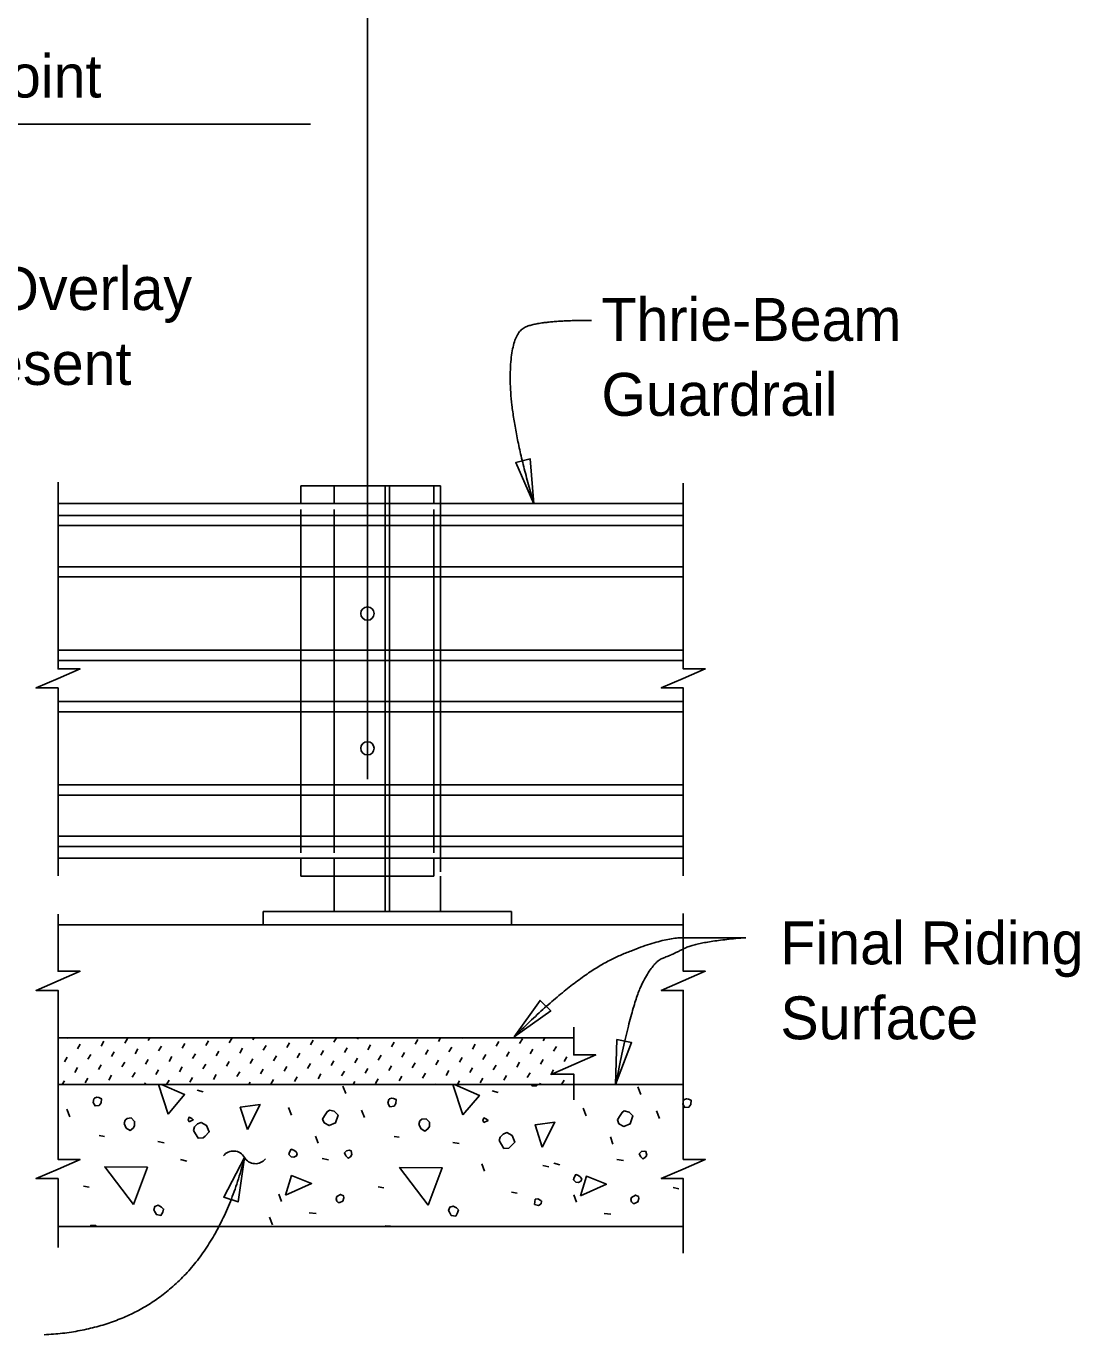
# Model space of a CAD drawing. Extents: x 21629.5 to 21698.8, y 56199.1 to 56237.6.
# Drawn here: x 21645.71 to 21650.66, y 56213.58 to 56219.73 of the extents above; entities that cross this region are included whole.
import ezdxf

# ---------------------------------------------------------------- set-up
doc = ezdxf.new("R2010")
doc.units = 0
for name, color, linetype in [('Dimension', 7, 'Continuous'), ('ExistSuperStruct', 7, 'Continuous'), ('Miscellaneous', 7, 'Continuous'), ('SteelMisc', 7, 'Continuous'), ('SteelMisc_h', 7, 'Continuous'), ('TextStructures', 7, 'Continuous')]:
    doc.layers.add(name, color=color, linetype=linetype)

msp = doc.modelspace()

# ---------------------------------------------------------------- linework, layer by layer
at = {"layer": 'Dimension'}
for p, q in [((21647.316, 56216.1894), (21647.316, 56231.405)), ((21647.048, 56219.267), (21641.4764, 56219.267))]:
    msp.add_line(p, q, dxfattribs=at)
for points in [[(21648.0978, 56217.4829), (21648.0807, 56217.6934), (21648.0123, 56217.676)], [(21648.0044, 56214.9776), (21648.1766, 56215.0999), (21648.1267, 56215.1498)], [(21648.4818, 56214.754), (21648.5565, 56214.9516), (21648.4873, 56214.9652)], [(21646.739, 56214.4119), (21646.7086, 56214.2029), (21646.6414, 56214.2246)]]:
    msp.add_lwpolyline(points, close=True, dxfattribs=at)
for points in [[(21645.8635, 56215.734), (21645.8635, 56216.6173), (21645.7601, 56216.6173), (21645.8635, 56216.6623), (21645.9668, 56216.7073), (21645.8635, 56216.7073), (21645.8635, 56217.5837)], [(21648.799, 56215.734), (21648.799, 56216.6173), (21648.6957, 56216.6173), (21648.799, 56216.6623), (21648.9023, 56216.7073), (21648.799, 56216.7073), (21648.799, 56217.5802)], [(21645.8635, 56214.7266), (21645.8635, 56215.1966), (21645.7601, 56215.1966), (21645.8635, 56215.2416), (21645.9668, 56215.2866), (21645.8635, 56215.2866), (21645.8635, 56215.5547)], [(21648.799, 56214.7266), (21648.799, 56215.1966), (21648.6957, 56215.1966), (21648.799, 56215.2416), (21648.9023, 56215.2866), (21648.799, 56215.2866), (21648.799, 56215.5576)], [(21648.2848, 56214.6826), (21648.2848, 56214.8035), (21648.1815, 56214.8035), (21648.2848, 56214.8485), (21648.3882, 56214.8935), (21648.2848, 56214.8935), (21648.2848, 56215.024)], [(21645.8635, 56213.9879), (21645.8635, 56214.3122), (21645.7601, 56214.3122), (21645.8635, 56214.3572), (21645.9668, 56214.4022), (21645.8635, 56214.4022), (21645.8635, 56214.7266)], [(21648.799, 56213.9615), (21648.799, 56214.3122), (21648.6957, 56214.3122), (21648.799, 56214.3572), (21648.9023, 56214.4022), (21648.799, 56214.4022), (21648.799, 56214.7266)]]:
    msp.add_lwpolyline(points, dxfattribs=at)
for centre, start, end in [((21646.6867, 56214.3823), 30.00813, 141.73535), ((21646.7899, 56214.4419), 210.00813, 321.73535)]:
    msp.add_arc(centre, 0.0596, start, end, dxfattribs=at)
for points in [[(21648.3681, 56218.3445), (21648.1279, 56218.3445), (21647.9865, 56218.2809), (21647.9865, 56217.8602), (21648.0978, 56217.4829)], [(21649.0928, 56215.4442), (21648.902, 56215.4442), (21648.697, 56215.4442), (21648.3013, 56215.2746), (21648.0044, 56214.9776)], [(21649.0928, 56215.4442), (21648.867, 56215.4258), (21648.7433, 56215.3622), (21648.6602, 56215.3321), (21648.556, 56215.1323), (21648.4818, 56214.754)], [(21646.739, 56214.4119), (21646.5384, 56213.6173), (21645.7979, 56213.5783)]]:
    msp.add_open_spline(points, degree=2, dxfattribs=at)
at = {"layer": 'ExistSuperStruct'}
for p, q in [((21645.8634, 56215.5045), (21648.799, 56215.5045)), ((21648.2848, 56214.9735), (21645.8634, 56214.9735)), ((21648.799, 56214.7545), (21645.8634, 56214.7545)), ((21645.8634, 56214.0879), (21648.799, 56214.0879))]:
    msp.add_line(p, q, dxfattribs=at)
at = {"layer": 'Miscellaneous'}
for p, q in [((21647.0035, 56217.5671), (21647.6285, 56217.5671)), ((21647.0035, 56217.5671), (21647.0035, 56217.4838)), ((21647.6285, 56217.5671), (21647.6285, 56217.4838)), ((21647.0035, 56217.4552), (21647.0035, 56215.8434)), ((21647.6285, 56217.4552), (21647.6285, 56215.8434)), ((21647.0035, 56215.7338), (21647.0035, 56215.8171)), ((21647.6285, 56215.7338), (21647.6285, 56215.8171)), ((21647.0035, 56215.7338), (21647.6285, 56215.7338)), ((21645.9059, 56214.9708), (21645.9075, 56214.9735)), ((21646.0654, 56214.9349), (21646.0784, 56214.9573)), ((21646.176, 56214.9478), (21646.189, 56214.9702)), ((21646.2867, 56214.9608), (21646.294, 56214.9735)), ((21646.5568, 56214.9379), (21646.5697, 56214.9603)), ((21646.6674, 56214.9509), (21646.6804, 56214.9733)), ((21646.778, 56214.9638), (21646.7836, 56214.9735)), ((21646.9375, 56214.928), (21646.9505, 56214.9504)), ((21647.0481, 56214.9409), (21647.0611, 56214.9633)), ((21647.1588, 56214.9539), (21647.1701, 56214.9735)), ((21647.2694, 56214.9668), (21647.2733, 56214.9735)), ((21647.4289, 56214.931), (21647.4418, 56214.9534)), ((21647.5395, 56214.9439), (21647.5525, 56214.9663)), ((21647.6501, 56214.9569), (21647.6597, 56214.9735)), ((21647.7608, 56214.9699), (21647.7629, 56214.9735)), ((21647.9202, 56214.934), (21647.9332, 56214.9564)), ((21648.0309, 56214.947), (21648.0438, 56214.9694)), ((21648.1415, 56214.9599), (21648.1494, 56214.9735)), ((21648.2521, 56214.9729), (21648.2525, 56214.9735)), ((21645.9548, 56214.9219), (21645.9677, 56214.9443)), ((21646.0036, 56214.8731), (21646.0166, 56214.8955)), ((21646.1142, 56214.886), (21646.1272, 56214.9084)), ((21646.2249, 56214.899), (21646.2378, 56214.9214)), ((21646.3355, 56214.912), (21646.3485, 56214.9344)), ((21646.4461, 56214.9249), (21646.4591, 56214.9473)), ((21646.495, 56214.8761), (21646.5079, 56214.8985)), ((21646.6056, 56214.8891), (21646.6186, 56214.9115)), ((21646.7162, 56214.902), (21646.7292, 56214.9244)), ((21646.8269, 56214.915), (21646.8398, 56214.9374)), ((21646.8757, 56214.8662), (21646.8887, 56214.8886)), ((21646.9863, 56214.8791), (21646.9993, 56214.9015)), ((21647.097, 56214.8921), (21647.1099, 56214.9145)), ((21647.2076, 56214.9051), (21647.2206, 56214.9274)), ((21647.3182, 56214.918), (21647.3312, 56214.9404)), ((21647.3671, 56214.8692), (21647.38, 56214.8916)), ((21647.4777, 56214.8821), (21647.4907, 56214.9045)), ((21647.5883, 56214.8951), (21647.6013, 56214.9175)), ((21647.699, 56214.9081), (21647.7119, 56214.9305)), ((21647.8096, 56214.921), (21647.8226, 56214.9434)), ((21647.8584, 56214.8722), (21647.8714, 56214.8946)), ((21647.9691, 56214.8852), (21647.982, 56214.9076)), ((21648.0797, 56214.8981), (21648.0927, 56214.9205)), ((21648.1903, 56214.9111), (21648.2033, 56214.9335)), ((21645.893, 56214.8601), (21645.9059, 56214.8825)), ((21645.9418, 56214.8113), (21645.9548, 56214.8337)), ((21646.0524, 56214.8243), (21646.0654, 56214.8466)), ((21646.1631, 56214.8372), (21646.176, 56214.8596)), ((21646.2737, 56214.8502), (21646.2867, 56214.8726)), ((21646.3843, 56214.8631), (21646.3973, 56214.8855)), ((21646.4332, 56214.8143), (21646.4461, 56214.8367)), ((21646.5438, 56214.8273), (21646.5568, 56214.8497)), ((21646.6544, 56214.8402), (21646.6674, 56214.8626)), ((21646.7651, 56214.8532), (21646.778, 56214.8756)), ((21646.9245, 56214.8173), (21646.9375, 56214.8397)), ((21647.0352, 56214.8303), (21647.0481, 56214.8527)), ((21647.1458, 56214.8433), (21647.1588, 56214.8656)), ((21647.2564, 56214.8562), (21647.2694, 56214.8786)), ((21647.3053, 56214.8074), (21647.3182, 56214.8298)), ((21647.4159, 56214.8203), (21647.4289, 56214.8427)), ((21647.5265, 56214.8333), (21647.5395, 56214.8557)), ((21647.6372, 56214.8463), (21647.6501, 56214.8687)), ((21647.7478, 56214.8592), (21647.7608, 56214.8816)), ((21647.7966, 56214.8104), (21647.8096, 56214.8328)), ((21647.9073, 56214.8234), (21647.9202, 56214.8458)), ((21648.0179, 56214.8363), (21648.0309, 56214.8587)), ((21648.1285, 56214.8493), (21648.1415, 56214.8717)), ((21648.2392, 56214.8623), (21648.2521, 56214.8846)), ((21645.8829, 56214.7545), (21645.893, 56214.7719)), ((21645.9906, 56214.7625), (21646.0036, 56214.7848)), ((21646.1013, 56214.7754), (21646.1142, 56214.7978)), ((21646.2119, 56214.7884), (21646.2249, 56214.8108)), ((21646.3225, 56214.8013), (21646.3355, 56214.8237)), ((21646.3726, 56214.7546), (21646.3843, 56214.7749)), ((21646.482, 56214.7655), (21646.495, 56214.7879)), ((21646.5926, 56214.7784), (21646.6056, 56214.8008)), ((21646.7033, 56214.7914), (21646.7162, 56214.8138)), ((21646.8139, 56214.8044), (21646.8269, 56214.8268)), ((21646.8627, 56214.7555), (21646.8757, 56214.7779)), ((21646.9734, 56214.7685), (21646.9863, 56214.7909)), ((21647.084, 56214.7815), (21647.097, 56214.8038)), ((21647.1946, 56214.7944), (21647.2076, 56214.8168)), ((21647.2488, 56214.7547), (21647.2564, 56214.768)), ((21647.3541, 56214.7585), (21647.3671, 56214.7809)), ((21647.4647, 56214.7715), (21647.4777, 56214.7939)), ((21647.5754, 56214.7845), (21647.5883, 56214.8069)), ((21647.686, 56214.7974), (21647.699, 56214.8198)), ((21647.7384, 56214.7548), (21647.7478, 56214.771)), ((21647.8455, 56214.7616), (21647.8584, 56214.784)), ((21647.9561, 56214.7745), (21647.9691, 56214.7969)), ((21648.0667, 56214.7875), (21648.0797, 56214.8099)), ((21648.1774, 56214.8005), (21648.1903, 56214.8229)), ((21648.2281, 56214.7548), (21648.2392, 56214.774)), ((21646.2694, 56214.7546), (21646.2737, 56214.7619)), ((21646.517, 56214.7274), (21646.5453, 56214.7203)), ((21646.7591, 56214.7547), (21646.7651, 56214.765)), ((21647.1456, 56214.7547), (21647.1458, 56214.755)), ((21647.2153, 56214.7115), (21647.2011, 56214.7468)), ((21647.6353, 56214.7548), (21647.6372, 56214.758)), ((21647.9017, 56214.7239), (21647.93, 56214.7168)), ((21648.1249, 56214.7548), (21648.1285, 56214.7611)), ((21648.6, 56214.7079), (21648.5858, 56214.7433)), ((21646.9589, 56214.6107), (21646.9448, 56214.6461)), ((21648.3436, 56214.6072), (21648.3295, 56214.6425)), ((21645.9184, 56214.6025), (21645.9042, 56214.6379)), ((21647.303, 56214.599), (21647.2889, 56214.6343)), ((21648.6877, 56214.5954), (21648.6736, 56214.6308)), ((21646.0562, 56214.5141), (21646.081, 56214.5106)), ((21646.332, 56214.4858), (21646.3621, 56214.4805)), ((21647.0845, 56214.4781), (21647.0721, 56214.5117)), ((21647.4409, 56214.5106), (21647.4657, 56214.507)), ((21647.7167, 56214.4823), (21647.7467, 56214.477)), ((21648.4691, 56214.4746), (21648.4568, 56214.5082)), ((21646.4389, 56214.4019), (21646.4672, 56214.3949)), ((21647.1033, 56214.4063), (21647.1333, 56214.401)), ((21648.488, 56214.4027), (21648.518, 56214.3974)), ((21647.8652, 56214.3479), (21647.8528, 56214.3815)), ((21648.1392, 56214.3745), (21648.1675, 56214.3674)), ((21648.1916, 56214.3844), (21648.2199, 56214.3774)), ((21645.982, 56214.2772), (21646.0085, 56214.2719)), ((21647.3667, 56214.2737), (21647.3932, 56214.2684)), ((21646.913, 56214.2054), (21646.9006, 56214.239)), ((21647.9925, 56214.2489), (21648.019, 56214.2436)), ((21648.2977, 56214.2018), (21648.2853, 56214.2354)), ((21648.7514, 56214.2702), (21648.7779, 56214.2649)), ((21647.0432, 56214.1517), (21647.075, 56214.1482)), ((21646.8706, 56214.0958), (21646.8564, 56214.1311)), ((21648.4279, 56214.1482), (21648.4597, 56214.1447))]:
    msp.add_line(p, q, dxfattribs=at)
for points in [[(21646.3797, 56214.6149), (21646.3343, 56214.7545)], [(21646.3482, 56214.7545), (21646.4575, 56214.7068), (21646.3797, 56214.6149)], [(21647.7644, 56214.6113), (21647.7178, 56214.7545)], [(21647.7248, 56214.7545), (21647.8422, 56214.7033), (21647.7644, 56214.6113)], [(21648.0865, 56214.7545), (21648.0891, 56214.7486), (21648.0855, 56214.7521)], [(21648.0891, 56214.7486), (21648.1103, 56214.7486), (21648.1162, 56214.7545)], [(21646.028, 56214.6697), (21646.0368, 56214.6538), (21646.0562, 56214.6555), (21646.0651, 56214.6679), (21646.0669, 56214.6874), (21646.0545, 56214.6927), (21646.0456, 56214.6944), (21646.035, 56214.6909), (21646.0315, 56214.6874), (21646.028, 56214.6697)], [(21646.7521, 56214.5432), (21646.7185, 56214.6475), (21646.8122, 56214.6599), (21646.7521, 56214.5432)], [(21647.4126, 56214.6661), (21647.4215, 56214.6502), (21647.4409, 56214.652), (21647.4498, 56214.6644), (21647.4515, 56214.6838), (21647.4392, 56214.6891), (21647.4303, 56214.6909), (21647.4197, 56214.6874), (21647.4162, 56214.6838), (21647.4126, 56214.6661)], [(21648.7973, 56214.6626), (21648.8062, 56214.6467), (21648.8256, 56214.6485), (21648.8344, 56214.6608), (21648.8362, 56214.6803), (21648.8238, 56214.6856), (21648.815, 56214.6874), (21648.8044, 56214.6838), (21648.8009, 56214.6803), (21648.7973, 56214.6626)], [(21646.1729, 56214.5707), (21646.1835, 56214.5495), (21646.2012, 56214.5389), (21646.2153, 56214.5495), (21646.2224, 56214.5601), (21646.2224, 56214.5813), (21646.2065, 56214.5972), (21646.1871, 56214.5954), (21646.1782, 56214.5866), (21646.1729, 56214.5707)], [(21646.4787, 56214.5795), (21646.4982, 56214.5884), (21646.4911, 56214.5954), (21646.4787, 56214.6007), (21646.4734, 56214.5884), (21646.4787, 56214.5795)], [(21647.1127, 56214.5736), (21647.1357, 56214.5612), (21647.1658, 56214.5736), (21647.1782, 56214.6107), (21647.1605, 56214.6284), (21647.1375, 56214.6337), (21647.1269, 56214.6266), (21647.1145, 56214.6072), (21647.1057, 56214.5913), (21647.1127, 56214.5736)], [(21647.5576, 56214.5671), (21647.5682, 56214.5459), (21647.5859, 56214.5353), (21647.6, 56214.5459), (21647.6071, 56214.5565), (21647.6071, 56214.5778), (21647.5912, 56214.5937), (21647.5717, 56214.5919), (21647.5629, 56214.5831), (21647.5576, 56214.5671)], [(21647.8634, 56214.576), (21647.8829, 56214.5848), (21647.8758, 56214.5919), (21647.8634, 56214.5972), (21647.8581, 56214.5848), (21647.8634, 56214.576)], [(21648.4974, 56214.5701), (21648.5204, 56214.5577), (21648.5505, 56214.5701), (21648.5628, 56214.6072), (21648.5452, 56214.6249), (21648.5222, 56214.6302), (21648.5116, 56214.6231), (21648.4992, 56214.6036), (21648.4903, 56214.5877), (21648.4974, 56214.5701)], [(21646.4988, 56214.5389), (21646.5218, 56214.5018), (21646.5448, 56214.5036), (21646.5536, 56214.5124), (21646.5731, 56214.5319), (21646.5607, 56214.5619), (21646.5359, 56214.5761), (21646.5183, 56214.569), (21646.5041, 56214.5548), (21646.4988, 56214.5389)], [(21647.9341, 56214.4911), (21647.9571, 56214.454), (21647.9801, 56214.4558), (21647.9889, 56214.4646), (21648.0084, 56214.4841), (21647.996, 56214.5141), (21647.9713, 56214.5283), (21647.9536, 56214.5212), (21647.9394, 56214.507), (21647.9341, 56214.4911)], [(21648.1368, 56214.4605), (21648.1032, 56214.5648), (21648.1969, 56214.5771), (21648.1368, 56214.4605)], [(21646.9579, 56214.415), (21646.9702, 56214.4132), (21646.9826, 56214.4185), (21646.9861, 56214.4292), (21646.9808, 56214.438), (21646.9702, 56214.4451), (21646.9579, 56214.4504), (21646.9508, 56214.4362), (21646.9472, 56214.4256), (21646.9579, 56214.415)], [(21647.2146, 56214.4187), (21647.2253, 56214.408), (21647.2359, 56214.4151), (21647.2429, 56214.4257), (21647.2394, 56214.4434), (21647.2306, 56214.4452), (21647.2182, 56214.4434), (21647.2076, 56214.4328), (21647.2146, 56214.4187)], [(21648.5993, 56214.4151), (21648.6099, 56214.4045), (21648.6205, 56214.4116), (21648.6276, 56214.4222), (21648.6241, 56214.4399), (21648.6152, 56214.4416), (21648.6029, 56214.4399), (21648.5923, 56214.4293), (21648.5993, 56214.4151)], [(21646.2171, 56214.1906), (21646.0828, 56214.3674), (21646.2825, 56214.3656), (21646.2171, 56214.1906)], [(21647.6018, 56214.1871), (21647.4674, 56214.3639), (21647.6672, 56214.3621), (21647.6018, 56214.1871)], [(21646.9318, 56214.2348), (21646.9601, 56214.3267), (21647.0538, 56214.2896), (21646.9318, 56214.2348)], [(21648.2941, 56214.2961), (21648.3065, 56214.2943), (21648.3189, 56214.2996), (21648.3224, 56214.3102), (21648.3171, 56214.319), (21648.3065, 56214.3261), (21648.2941, 56214.3314), (21648.2871, 56214.3173), (21648.2835, 56214.3067), (21648.2941, 56214.2961)], [(21648.3165, 56214.2313), (21648.3448, 56214.3232), (21648.4385, 56214.2861), (21648.3165, 56214.2313)], [(21647.1793, 56214.1995), (21647.1864, 56214.1995), (21647.2005, 56214.2065), (21647.2058, 56214.2224), (21647.204, 56214.2313), (21647.1899, 56214.2383), (21647.1722, 56214.2277), (21647.1687, 56214.2171), (21647.1722, 56214.2065), (21647.1793, 56214.1995)], [(21648.1003, 56214.1906), (21648.1197, 56214.1853), (21648.1321, 56214.1941), (21648.1339, 56214.2065), (21648.1304, 56214.2101), (21648.1162, 56214.2171), (21648.1038, 56214.2154), (21648.1021, 56214.203), (21648.1003, 56214.1906)], [(21648.564, 56214.1959), (21648.571, 56214.1959), (21648.5852, 56214.203), (21648.5905, 56214.2189), (21648.5887, 56214.2277), (21648.5746, 56214.2348), (21648.5569, 56214.2242), (21648.5534, 56214.2136), (21648.5569, 56214.203), (21648.564, 56214.1959)], [(21646.3161, 56214.1588), (21646.3249, 56214.1429), (21646.3462, 56214.1393), (21646.355, 56214.1553), (21646.3585, 56214.1694), (21646.3497, 56214.1782), (21646.3338, 56214.1871), (21646.3179, 56214.1818), (21646.3126, 56214.1659), (21646.3161, 56214.1588)], [(21647.7008, 56214.1553), (21647.7096, 56214.1393), (21647.7308, 56214.1358), (21647.7397, 56214.1517), (21647.7432, 56214.1659), (21647.7344, 56214.1747), (21647.7185, 56214.1835), (21647.7026, 56214.1782), (21647.6972, 56214.1623), (21647.7008, 56214.1553)], [(21646.0414, 56214.0879), (21646.0403, 56214.0916), (21646.0174, 56214.0934), (21646.0155, 56214.0879)], [(21647.4251, 56214.0879), (21647.425, 56214.0881), (21647.402, 56214.0898), (21647.4014, 56214.0879)]]:
    msp.add_lwpolyline(points, dxfattribs=at)
at = {"layer": 'SteelMisc'}
for p, q in [((21647.1598, 56217.5671), (21647.6598, 56217.5671)), ((21647.1598, 56217.5671), (21647.1598, 56217.4838)), ((21648.799, 56217.4837), (21645.8634, 56217.4837)), ((21645.8634, 56217.4282), (21648.799, 56217.4282)), ((21645.8634, 56217.38), (21648.799, 56217.38)), ((21645.8634, 56217.1871), (21648.799, 56217.1871)), ((21645.8634, 56217.1389), (21648.799, 56217.1389)), ((21645.8634, 56216.795), (21648.799, 56216.795)), ((21645.8634, 56216.7467), (21648.799, 56216.7467)), ((21645.8634, 56216.5539), (21648.799, 56216.5539)), ((21645.8634, 56216.5058), (21648.799, 56216.5058)), ((21645.8634, 56216.1618), (21648.799, 56216.1618)), ((21645.8634, 56216.1136), (21648.799, 56216.1136)), ((21645.8634, 56215.9208), (21648.799, 56215.9208)), ((21645.8634, 56215.8726), (21648.799, 56215.8726)), ((21648.799, 56215.817), (21645.8634, 56215.817)), ((21647.1598, 56215.8171), (21647.1598, 56215.5671)), ((21647.6598, 56215.7338), (21647.6598, 56215.5671)), ((21646.8264, 56215.5671), (21647.9931, 56215.5671)), ((21646.8264, 56215.5046), (21646.8264, 56215.5671)), ((21647.1598, 56215.5671), (21647.6598, 56215.5671)), ((21647.9931, 56215.5671), (21647.9931, 56215.5046)), ((21646.8264, 56215.5046), (21647.9931, 56215.5046))]:
    msp.add_line(p, q, dxfattribs=at)
for centre in [(21647.316, 56216.967), (21647.316, 56216.3339)]:
    msp.add_circle(centre, 0.0312, dxfattribs=at)
at = {"layer": 'SteelMisc_h'}
for p, q in [((21647.3994, 56215.5671), (21647.3994, 56217.5671)), ((21647.4202, 56215.5671), (21647.4202, 56217.5671)), ((21647.6598, 56217.5671), (21647.6598, 56215.7541)), ((21647.1598, 56217.4552), (21647.1598, 56215.8434))]:
    msp.add_line(p, q, dxfattribs=at)

# ---------------------------------------------------------------- texts
at = {"layer": 'Dimension'}
for s, p in [('Asphalt Overlay', (21644.5895, 56218.3932)), ('Thrie-Beam ', (21648.415, 56218.248)), ('when present', (21644.5895, 56218.0412)), ('Guardrail', (21648.415, 56217.896)), ('Final Riding ', (21649.2554, 56215.3188)), ('Surface', (21649.2554, 56214.9668))]:
    msp.add_text(s, height=0.2016, dxfattribs=at).set_placement(p)
at = {"layer": 'TextStructures'}
msp.add_text('Intermediate Deck Joint', height=0.2016, dxfattribs=at).set_placement((21643.2352, 56219.3914))

doc.saveas('drawing.dxf')
